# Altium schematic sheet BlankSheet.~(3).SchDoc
size 431 x 279 mm; Date: Not shown in title block; ApprovedBy: Not shown in title block; CheckedBy: Not shown in title block; Author: Not shown in title block; CompanyName: Not shown in title block; Engineer: Not shown in title block; Organization: Not shown in title block; Address1: Not shown in title block; Address2: Not shown in title block; Address3: Not shown in title block; Address4: Not shown in title block; DocumentNumber: 1; Revision: Use project parameter SCH_Rev; SheetNumber: 2; SheetTotal: 3; PageSetup: Record=PageOptions¦CenterHorizontal=True¦CenterVertical=True¦PrintScale=1.00¦XCorrection=1.00¦YCorrection=1.00¦PrintKind=0¦BorderSize=5000000¦LeftOffset=0¦BottomOffset=0¦Orientation=2¦PaperLength=1000¦PaperWidth=1000¦Scale=100¦PaperSource=15¦PrintQuality=600¦MediaType=1¦DitherType=10¦PaperKind=Letter¦PrintScaleMode=1
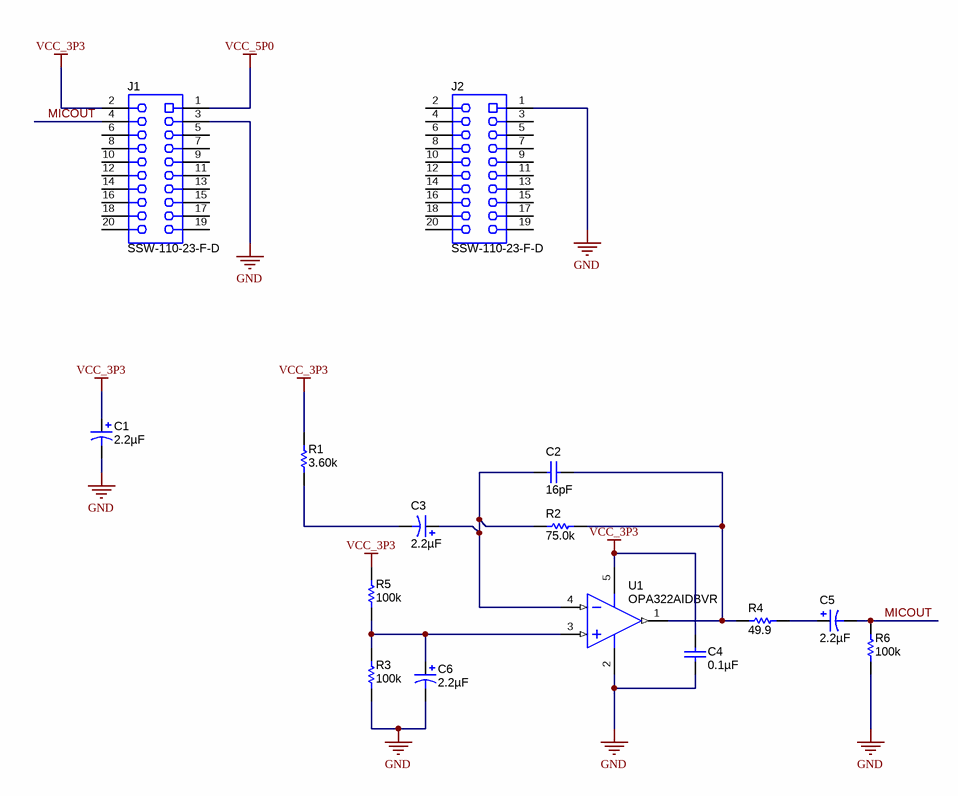
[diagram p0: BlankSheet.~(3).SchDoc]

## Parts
C1  ValueDisplayed: 2.2µF  [3216-18]  (hidden comment: TPSA225K010R1800)
C2  ValueDisplayed: 16pF  [0603]  (hidden comment: GRM1885C1H160JA01D)
C3  ValueDisplayed: 2.2µF  [3216-18]  (hidden comment: TPSA225K010R1800)
C4  ValueDisplayed: 0.1µF  [0603]  (hidden comment: 0603YC104JAT2A)
C5  ValueDisplayed: 2.2µF  [3216-18]  (hidden comment: TPSA225K010R1800)
C6  ValueDisplayed: 2.2µF  [3216-18]  (hidden comment: TPSA225K010R1800)
J1  SSW-110-23-F-D  [CONN_SSW-110-23-F-D]
J2  SSW-110-23-F-D  [CONN_SSW-110-23-F-D]
R1  ValueDisplayed: 3.60k  [0603]  (hidden comment: RC0603FR-073K6L)
R2  ValueDisplayed: 75.0k  [0603]  (hidden comment: RC0603FR-0775KL)
R3  ValueDisplayed: 100k  [0603]  (hidden comment: RC0603FR-07100KL)
R4  ValueDisplayed: 49.9  [0603]  (hidden comment: RC0603FR-0749R9L)
R5  ValueDisplayed: 100k  [0603]  (hidden comment: RC0603FR-07100KL)
R6  ValueDisplayed: 100k  [0603]  (hidden comment: RC0603FR-07100KL)
U1  OPA322AIDBVR  [DBV0005A_N]

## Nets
GND: C1.2(-) C4.2 C6.2(-) J1.3 J2.1 R3.1 R6.1 U1.2(V-)
VCC_3P3: C1.1(+) C4.1 J1.2 R1.2 R5.2 U1.5(V+)
VCC_5P0: J1.1
MICOUT: C5.2(-) J1.4 R6.2
NetC2_1: C2.1 R2.2 R4.1 U1.1(OUT)
NetC2_2: C2.2 C3.1(+) R2.1 U1.4(IN-)
NetC3_2: C3.2(-) R1.1
NetC5_1: C5.1(+) R4.2
NetC6_1: C6.1(+) R3.2 R5.1 U1.3(IN+)

Not connected (* = marked no-connect by the designer): J1 5 6 7 8 9 10 11 12 13 14 15 16 17 18 19 20; J2 2 3 4 5 6 7 8 9 10 11 12 13 14 15 16 17 18 19 20

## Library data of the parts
C1 C3 C5 C6 = TPSA225K010R1800: CAP, TA, 2.2 µF, 10 V, +/- 10%, 1.8 ohm, SMD; Manufacturer: AVX; Polarized: Y; CompType: Capacitor; Value: 2.2uF; U/M: EA; Cap_F: 0.0000022; Tolerance_%: 10; Value1: 1.8 ohm; Value2: 10V; ESR_ohm: 1.8; IRMS_A: 0.184; TaMin_C: -55; TaMax_C: 125; Cap_Case: A; AEC Category: Q200
C2 = GRM1885C1H160JA01D: CAP, CERM, 16 pF, 50 V, +/- 5%, C0G/NP0, 0603; Manufacturer: MuRata; Polarized: N; CompType: Capacitor; Value: 16pF; U/M: EA; Cap_F: 0.000000000016; Tolerance_%: 5; Value1: Unknown; VDC_V: 50; Value2: 50V; TaMin_C: -55; TaMax_C: 125; AEC Category: Q200
C4 = 0603YC104JAT2A: CAP, CERM, 0.1 µF, 16 V, +/- 5%, X7R, 0603; Manufacturer: AVX; Polarized: N; CompType: Capacitor; Value: 0.1uF; U/M: EA; Cap_F: 0.0000001; Tolerance_%: 5; ESR_ohm: 0.039; Value1: 0.039 ohm; VDC_V: 16; Value2: 16V; TaMin_C: -55; TaMax_C: 125; AEC Category: Q200
J1 J2 = SSW-110-23-F-D: Connector, Receptacle, 100mil, 10x2, Gold plated, TH; Manufacturer: Samtec; SymbolCreator: a0412235
R1 = RC0603FR-073K6L: RES, 3.60 k, 1%, 0.1 W, 0603; Manufacturer: Yageo America; CompType: Resistor; Value: 3.60k; Res_ohm: 3600; Value_Code: 3k60; Tolerance_%: 1; Power_W: 0.1; Value2: 0.1W; VDC_V: 150; TempCo: 200 ppm/C; U/M: EA; AEC Category: Q200
R2 = RC0603FR-0775KL: RES, 75.0 k, 1%, 0.1 W, 0603; Manufacturer: Yageo America; CompType: Resistor; Value: 75.0k; Res_ohm: 75000; Value_Code: 75k0; Tolerance_%: 1; Power_W: 0.1; Value2: 0.1W; VDC_V: 150; TempCo: 200 ppm/C; EIA_Code: E96; U/M: EA; AEC Category: Q200
R3 R5 R6 = RC0603FR-07100KL: RES, 100 k, 1%, 0.1 W, 0603; Manufacturer: Yageo America; CompType: Resistor; Value: 100k; Res_ohm: 100000; Tolerance_%: 1; Power_W: 0.1; Value2: 0.1W; VDC_V: 150; TempCo: 200 ppm/C; EIA_Code: E96; U/M: EA; AEC Category: Q200
R4 = RC0603FR-0749R9L: RES, 49.9, 1%, 0.1 W, 0603; Manufacturer: Yageo America; CompType: Resistor; Value: 49.9; Value_Code: 49R9; Tolerance_%: 1; Power_W: 0.1; Value2: 0.1W; VDC_V: 150; TempCo: 200 ppm/C; EIA_Code: E96; U/M: EA; AEC Category: Q200
U1 = OPA322AIDBVR: 20 MHz, Low Noise, RRIO, CMOS Operational Amplifier with Shutdown, 1.8 to 5.5 V, -40 to 125 degC, 5-pin SOT23 (DBV0005A), Green (RoHS & no Sb/Br); Manufacturer: Texas Instruments; Alternate PartNumber: Equivalent; CMRR(Min)(dB): 90; GBW(Typ)(MHz): 20; IIB(Max)(pA): 10; Iq per channel(Max)(mA): 1.9; Number of Channels: 1; Offset Drift(Typ)(uV/C): 1.8; Packing: LARGE T&R; Rating: Catalog; Sub Family: High Output Current Amplifier (>=50mA), Low Input Bias Current Amp (<=10pA), Low Noise Amp (<=10nV/rtHz), Low Supply Voltage Amplifier (<=2.7V), Precision Amplifier; Total Supply Voltage(Max)(+5V is 5, +/-5V is 10): 5.5; Vio (25C)(Max)(mV): 2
